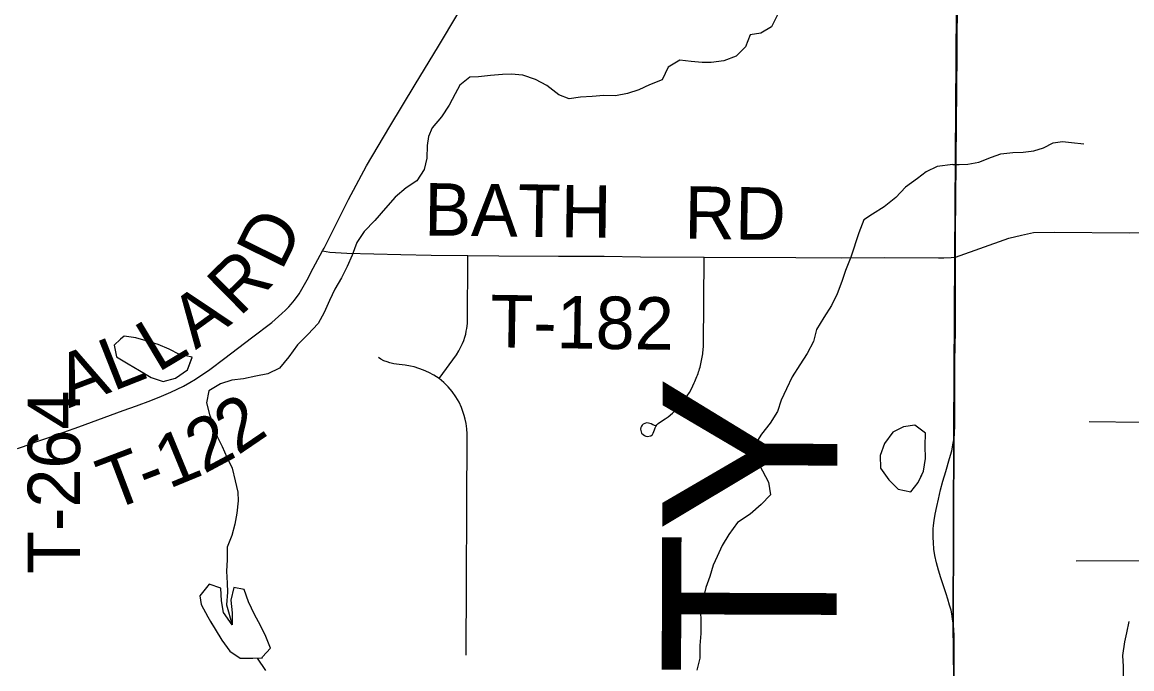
# Model space of a CAD drawing. Extents: x 0 to 34, y 0 to 22.
# Drawn here: x 6.974 to 8.175, y 16.35 to 17.051 of the extents above; entities that cross this region are included whole.
import ezdxf

# ---------------------------------------------------------------- set-up
doc = ezdxf.new("R2010")
doc.units = 0
for name, color, linetype in [('GM_X_Corporation', 7, 'Continuous'), ('GM_X_County_Road', 7, 'Continuous'), ('GM_X_County_Text', 7, 'Continuous'), ('GM_X_Minor_Lake', 7, 'Continuous'), ('GM_X_Minor_River', 7, 'Continuous'), ('GM_X_Township_Road', 7, 'Continuous'), ('GM_X_Township_Road_Text', 7, 'Continuous')]:
    doc.layers.add(name, color=color, linetype=linetype)

msp = doc.modelspace()

# ---------------------------------------------------------------- linework, layer by layer
at = {"layer": 'GM_X_Corporation'}
for points in [[(2.1, 20.9), (2.1, 14.1), (7.9734, 14.1), (7.9726, 14.5453), (7.9765, 15.2637), (7.9792, 15.5481), (7.979, 15.5988), (7.9808, 15.7192), (7.9807, 15.9078), (7.9821, 16.2487), (7.9825, 16.3395), (7.9818, 16.3982), (7.9825, 16.6077), (7.9838, 16.7968), (7.9877, 17.3871), (7.9891, 17.5498), (7.991, 17.7727), (7.9901, 18.1613)], [(7.9901, 18.1613), (7.991, 17.7727), (7.9891, 17.5498), (7.9877, 17.3871), (7.9838, 16.7968), (7.9825, 16.6077), (7.9818, 16.3982), (7.9825, 16.3395), (7.9821, 16.2487), (7.9807, 15.9078), (7.9808, 15.7192), (7.979, 15.5988), (7.9792, 15.5481), (7.9765, 15.2637), (7.9726, 14.5453), (7.9734, 14.1), (8.9, 14.1), (8.9, 20.9)], [(7.9901, 18.1613), (7.991, 17.7727), (7.9891, 17.5498), (7.9877, 17.3871), (7.9838, 16.7968), (7.9825, 16.6077), (7.9818, 16.3982), (7.9825, 16.3395), (7.9821, 16.2487), (7.9807, 15.9078), (7.9808, 15.7192), (7.979, 15.5988), (7.9792, 15.5481), (7.9765, 15.2637), (7.9726, 14.5453), (8.3169, 14.5418), (8.5518, 14.5426), (8.5844, 14.5431), (8.8409, 14.5545), (8.9, 14.5547), (8.9, 19.1229)], [(7.9901, 18.1613), (7.991, 17.7727), (7.9891, 17.5498), (7.9877, 17.3871), (7.9838, 16.7968), (7.9825, 16.6077), (7.9818, 16.3982), (7.9825, 16.3395), (7.9821, 16.2487), (7.9807, 15.9078), (7.9808, 15.7192), (7.979, 15.5988), (7.9792, 15.5481), (7.9765, 15.2637), (7.9726, 14.5453), (7.0871, 14.5429), (7.0197, 14.5427), (6.4941, 14.5412), (6.1476, 14.5397), (5.4644, 14.5374), (4.5212, 14.531)]]:
    msp.add_lwpolyline(points, dxfattribs=at)
at = {"layer": 'GM_X_County_Road'}
for p, q in [((7.9845, 16.7962), (7.9845, 16.7972)), ((7.9845, 16.7782), (7.9845, 16.7962)), ((7.983, 16.3802), (7.983, 16.3839))]:
    msp.add_line(p, q, dxfattribs=at)
for points in [[(7.9845, 16.7972), (7.9845, 16.8156), (7.985, 16.8666), (7.9851, 16.8923), (7.9853, 16.91), (7.9857, 16.9319), (7.9859, 16.9865), (7.9861, 17.0083), (7.9861, 17.0387), (7.9865, 17.06), (7.9862, 17.0801), (7.9861, 17.1071), (7.9863, 17.1552), (7.9869, 17.2019), (7.9869, 17.2365), (7.9873, 17.288), (7.9874, 17.3067), (7.9876, 17.3377), (7.9881, 17.3757), (7.9881, 17.382), (7.9881, 17.3883)], [(7.9845, 16.7962), (8.0423, 16.8166), (8.0561, 16.8201), (8.0688, 16.8228), (8.0916, 16.8232), (8.1729, 16.8224), (8.4609, 16.8258), (8.5768, 16.8284), (8.7668, 16.8308), (8.9, 16.8327)], [(7.9834, 16.6076), (7.9836, 16.6112), (7.9838, 16.6294), (7.9839, 16.6629), (7.9838, 16.6837), (7.9844, 16.7161), (7.9845, 16.744), (7.9845, 16.7782)], [(7.983, 16.3839), (7.9829, 16.3858), (7.9826, 16.393), (7.9819, 16.3995), (7.9813, 16.4041), (7.9804, 16.4098), (7.9796, 16.4138), (7.978, 16.4192), (7.976, 16.4257), (7.9743, 16.4314), (7.9687, 16.4487), (7.9661, 16.457), (7.9638, 16.465), (7.9621, 16.4728), (7.9611, 16.4798), (7.9605, 16.4869), (7.9602, 16.4924), (7.9603, 16.4985), (7.9604, 16.5019), (7.9607, 16.5053), (7.9614, 16.5107), (7.9625, 16.5177), (7.9642, 16.5261), (7.9659, 16.534), (7.9684, 16.5442), (7.9708, 16.5535), (7.9739, 16.564), (7.9781, 16.578), (7.9804, 16.5862), (7.9821, 16.5948), (7.9829, 16.6)], [(7.9829, 16.6), (7.9833, 16.6043), (7.9834, 16.6076)], [(7.9831, 16.3386), (7.9832, 16.3526), (7.983, 16.3802)]]:
    msp.add_lwpolyline(points, dxfattribs=at)
at = {"layer": 'GM_X_Minor_Lake'}
for points in [[(7.0802, 16.7072), (7.073, 16.7009), (7.0757, 16.688), (7.0882, 16.6807), (7.1008, 16.6732), (7.1134, 16.6659), (7.1263, 16.6614), (7.1396, 16.6652), (7.1525, 16.674), (7.1575, 16.6877)], [(7.0802, 16.7072), (7.073, 16.7009), (7.0757, 16.688), (7.0882, 16.6807), (7.1008, 16.6732), (7.1134, 16.6659), (7.1263, 16.6614), (7.1396, 16.6652), (7.1525, 16.674), (7.1575, 16.6876)], [(7.1575, 16.6877), (7.1441, 16.6907), (7.1327, 16.6964), (7.1209, 16.7017), (7.108, 16.7055), (7.0966, 16.7089), (7.084, 16.7104), (7.0802, 16.7072)], [(7.1575, 16.6877), (7.1441, 16.6907), (7.1327, 16.6964), (7.1209, 16.7017), (7.108, 16.7055), (7.0966, 16.7089), (7.084, 16.7104), (7.0802, 16.7072)], [(7.9404, 16.6141), (7.9281, 16.6122), (7.9167, 16.6065), (7.9076, 16.5943), (7.903, 16.5814), (7.9034, 16.5677), (7.9122, 16.5548), (7.9225, 16.5449), (7.9362, 16.5419), (7.9442, 16.5521), (7.9498, 16.5643)], [(7.9403, 16.6141), (7.9281, 16.6122), (7.9167, 16.6065), (7.9076, 16.5943), (7.903, 16.5814), (7.9034, 16.5677), (7.9122, 16.5548), (7.9225, 16.5449), (7.9362, 16.5419), (7.9442, 16.5521), (7.948, 16.5604)], [(7.9478, 16.5599), (7.9498, 16.5643), (7.9521, 16.578), (7.9517, 16.5917), (7.9521, 16.6054), (7.9404, 16.6142)], [(7.9498, 16.5643), (7.9498, 16.5643), (7.9521, 16.578), (7.9517, 16.5917), (7.9521, 16.6054), (7.9404, 16.6141)], [(7.2336, 16.3621), (7.234, 16.363), (7.2424, 16.3725), (7.2374, 16.3851), (7.2317, 16.3972), (7.2252, 16.409), (7.2187, 16.4227), (7.2141, 16.436), (7.2027, 16.4383), (7.1997, 16.4246), (7.2009, 16.4109), (7.2009, 16.3979), (7.1917, 16.4112), (7.1894, 16.4238), (7.1887, 16.4375), (7.1761, 16.442), (7.1658, 16.4291)], [(7.2336, 16.3621), (7.234, 16.363), (7.2424, 16.3725), (7.2374, 16.3851), (7.2317, 16.3972), (7.2252, 16.409), (7.2187, 16.4227), (7.2141, 16.436), (7.2027, 16.4383), (7.1997, 16.4246), (7.2009, 16.4109), (7.2009, 16.3979), (7.1917, 16.4112), (7.1894, 16.4238), (7.1887, 16.4375), (7.1761, 16.442), (7.1658, 16.4291)], [(7.1658, 16.4291), (7.1674, 16.42), (7.1746, 16.4063), (7.1776, 16.4013)], [(7.1771, 16.4017), (7.1826, 16.393), (7.1899, 16.3812), (7.1983, 16.3694), (7.2097, 16.3618), (7.2234, 16.3615), (7.2337, 16.3621)], [(7.1776, 16.4013), (7.1826, 16.393), (7.1899, 16.3812), (7.1983, 16.3694), (7.2097, 16.3618), (7.2234, 16.3615), (7.2336, 16.3621)]]:
    msp.add_lwpolyline(points, dxfattribs=at)
at = {"layer": 'GM_X_Minor_River'}
for points in [[(7.7916, 17.0588), (7.7851, 17.0459), (7.7737, 17.039), (7.7619, 17.0371), (7.757, 17.0242), (7.7468, 17.0139), (7.7334, 17.009), (7.7198, 17.007), (7.7102, 17.007), (7.6981, 17.0082), (7.6859, 17.0097), (7.6733, 17.002), (7.6669, 16.9883), (7.6532, 16.983), (7.6414, 16.9773), (7.6292, 16.9735), (7.6163, 16.9708), (7.6034, 16.9715), (7.5908, 16.9704), (7.5783, 16.9696), (7.5661, 16.9677), (7.5547, 16.9722), (7.5417, 16.9821), (7.5295, 16.9885), (7.5158, 16.9935), (7.5033, 16.9946), (7.4938, 16.9942), (7.4808, 16.9931), (7.4679, 16.9915), (7.4584, 16.9911), (7.4477, 16.9827), (7.4424, 16.9732), (7.436, 16.9607), (7.4276, 16.9481), (7.4177, 16.9363), (7.4136, 16.9268), (7.4121, 16.9173), (7.4117, 16.9036), (7.4091, 16.891), (7.4011, 16.8789), (7.3893, 16.8713), (7.3775, 16.861), (7.3669, 16.8492), (7.3555, 16.8358), (7.3441, 16.824), (7.3361, 16.8119), (7.3308, 16.7985), (7.3255, 16.786), (7.3194, 16.7738), (7.3122, 16.7616), (7.3065, 16.7491), (7.3005, 16.7361), (7.294, 16.7243), (7.283, 16.7125), (7.2716, 16.7011), (7.2625, 16.6882), (7.2522, 16.676), (7.2397, 16.6699), (7.2267, 16.6672), (7.2134, 16.6645), (7.2005, 16.663), (7.1883, 16.6588), (7.1758, 16.6512), (7.1731, 16.6383), (7.1766, 16.6257), (7.1808, 16.6139), (7.1846, 16.6018), (7.1903, 16.5911), (7.1953, 16.5793), (7.201, 16.5676), (7.2041, 16.5539), (7.2071, 16.5417), (7.2075, 16.5322), (7.206, 16.5189), (7.2038, 16.5067), (7.2007, 16.4945), (7.1954, 16.482), (7.1955, 16.4683), (7.1947, 16.4561), (7.1955, 16.4428), (7.1959, 16.4333), (7.1948, 16.4196)], [(7.9816, 16.8965), (7.9884, 16.8965), (7.9978, 16.897), (8.0096, 16.899), (8.0236, 16.9044), (8.0334, 16.9083), (8.0467, 16.9096), (8.0577, 16.9101), (8.0694, 16.9113), (8.0797, 16.9148), (8.0902, 16.9202), (8.1005, 16.9215), (8.11, 16.9204), (8.1233, 16.919)], [(7.9816, 16.8965), (7.9646, 16.8944), (7.9528, 16.8887), (7.9433, 16.8814), (7.9304, 16.8719), (7.9197, 16.8609), (7.9072, 16.8506), (7.8946, 16.8426), (7.8851, 16.8365), (7.8798, 16.8224), (7.8711, 16.7962), (7.8654, 16.7817), (7.8613, 16.7699), (7.8563, 16.7566), (7.8503, 16.7437), (7.8419, 16.7307), (7.8339, 16.7178), (7.8305, 16.7049), (7.8237, 16.6919), (7.8157, 16.6794), (7.8074, 16.6664), (7.8013, 16.6535), (7.7956, 16.6413), (7.7915, 16.6291), (7.7839, 16.6162), (7.7744, 16.6044), (7.7656, 16.5907), (7.7691, 16.5774), (7.7756, 16.5645), (7.7821, 16.5523), (7.784, 16.5386), (7.7741, 16.5283), (7.7619, 16.5177), (7.7483, 16.5085), (7.7391, 16.4956), (7.7316, 16.4838), (7.7262, 16.472), (7.7221, 16.4625), (7.7183, 16.4503), (7.7141, 16.4381), (7.7111, 16.426), (7.7084, 16.4119), (7.7088, 16.4024), (7.7085, 16.3883), (7.7077, 16.3754), (7.7074, 16.3617), (7.7044, 16.3488)], [(7.1948, 16.4196), (7.2009, 16.3979)], [(8.1664, 16.3397), (8.1663, 16.3526), (8.1658, 16.3647), (8.168, 16.3792), (8.1701, 16.3891), (8.1727, 16.4013)], [(7.2375, 16.3482), (7.2285, 16.3618)]]:
    msp.add_lwpolyline(points, dxfattribs=at)
at = {"layer": 'GM_X_Township_Road'}
for points in [[(6.9685, 16.5887), (6.9748, 16.5909), (6.9882, 16.5959), (7.0025, 16.6009), (7.0349, 16.6125), (7.0831, 16.6299), (7.0974, 16.635), (7.1128, 16.641), (7.1245, 16.6456), (7.1346, 16.65), (7.1415, 16.6533), (7.1481, 16.6565), (7.1551, 16.6602), (7.1614, 16.6641), (7.1767, 16.6743), (7.1932, 16.6868), (7.222, 16.7086), (7.2438, 16.7252), (7.2549, 16.735), (7.2588, 16.7386), (7.2623, 16.7423), (7.2649, 16.7452), (7.2684, 16.7495), (7.2734, 16.7566), (7.2822, 16.7716), (7.2888, 16.7843), (7.2989, 16.803), (7.3005, 16.8059), (7.327, 16.8588), (7.3465, 16.8952), (7.3716, 16.9378), (7.3992, 16.9832), (7.4245, 17.0249), (7.4454, 17.0598)], [(7.2989, 16.803), (7.3067, 16.8017), (7.3252, 16.8004), (7.3837, 16.7989), (7.4166, 16.7984), (7.4563, 16.7978), (7.4898, 16.7977), (7.5543, 16.7974), (7.6038, 16.7972), (7.6432, 16.7964), (7.7122, 16.796), (7.8117, 16.7958), (7.8613, 16.7956), (7.9081, 16.7957), (7.966, 16.7953), (7.9717, 16.7954), (7.9799, 16.7957), (7.9845, 16.7962)], [(7.4251, 16.6648), (7.4439, 16.6903), (7.4465, 16.6947), (7.4487, 16.699), (7.4505, 16.7027), (7.4518, 16.7058), (7.4531, 16.7095), (7.454, 16.7127), (7.4546, 16.7159), (7.4552, 16.719), (7.4559, 16.7243), (7.4563, 16.7978)], [(7.6594, 16.6133), (7.6568, 16.6145), (7.6547, 16.6155), (7.652, 16.6163), (7.6499, 16.6165), (7.6478, 16.616), (7.6463, 16.6153), (7.6451, 16.6142), (7.6443, 16.613), (7.6436, 16.6115), (7.6434, 16.6098), (7.6435, 16.6085), (7.6439, 16.607), (7.6445, 16.6055), (7.6462, 16.6039), (7.6475, 16.603), (7.6491, 16.6021), (7.6504, 16.6019), (7.6546, 16.6026), (7.6562, 16.6042), (7.6569, 16.6054), (7.6578, 16.6072), (7.6585, 16.609), (7.6592, 16.6113), (7.6598, 16.6128), (7.661, 16.6146), (7.6624, 16.6158), (7.665, 16.6176), (7.67, 16.6209), (7.6732, 16.6232), (7.6779, 16.6271), (7.6829, 16.6322), (7.6867, 16.6362), (7.6914, 16.6423), (7.6962, 16.6495), (7.6988, 16.6542), (7.7001, 16.6569), (7.7015, 16.66), (7.7022, 16.6616), (7.703, 16.6633), (7.7037, 16.665), (7.7044, 16.6667), (7.705, 16.6684), (7.7056, 16.6701), (7.7062, 16.6718), (7.7068, 16.6735), (7.7073, 16.6753), (7.7078, 16.677), (7.7083, 16.6788), (7.7087, 16.6806), (7.7091, 16.6823), (7.7095, 16.6841), (7.7098, 16.6859), (7.7102, 16.6877), (7.7104, 16.6895), (7.7107, 16.6913), (7.7109, 16.6931), (7.7111, 16.6949), (7.7112, 16.6967), (7.7114, 16.6985), (7.7115, 16.7003), (7.7122, 16.796)], [(7.4545, 16.3648), (7.4554, 16.6049), (7.455, 16.6102), (7.4544, 16.616), (7.4534, 16.6208), (7.4524, 16.6245), (7.4513, 16.628), (7.4495, 16.6332), (7.4468, 16.6392), (7.4433, 16.645), (7.4393, 16.6507), (7.4349, 16.6558), (7.4301, 16.6605), (7.4251, 16.6648), (7.4194, 16.6683), (7.414, 16.6711), (7.4083, 16.6737), (7.4033, 16.6756), (7.3982, 16.6772), (7.3943, 16.6782), (7.3885, 16.6792), (7.3818, 16.6799), (7.3762, 16.6807), (7.3719, 16.6817), (7.3688, 16.6828), (7.3654, 16.684), (7.3622, 16.6858), (7.3595, 16.6875)], [(8.2836, 16.4691), (8.2836, 16.5301), (8.2817, 16.5425), (8.278, 16.5574), (8.2748, 16.5722), (8.2697, 16.5855), (8.2652, 16.593), (8.26, 16.5996), (8.2543, 16.6051), (8.2463, 16.6114), (8.237, 16.6146), (8.2266, 16.6169), (8.2137, 16.6178), (8.1868, 16.6171), (8.1292, 16.6177)], [(8.1151, 16.4672), (8.2497, 16.4676), (8.2836, 16.4691), (8.2983, 16.469), (8.3072, 16.4704), (8.3148, 16.4727), (8.3204, 16.4754), (8.3257, 16.4778), (8.3363, 16.4814), (8.3466, 16.483), (8.3726, 16.4831), (8.4128, 16.4841), (8.4392, 16.4844)]]:
    msp.add_lwpolyline(points, dxfattribs=at)

# ---------------------------------------------------------------- texts
at = {"layer": 'GM_X_County_Text'}
msp.add_text('MEDINA COUNTY', height=0.189394, rotation=89.8023, dxfattribs=at).set_placement((7.8494, 14.542))
at = {"layer": 'GM_X_Township_Road_Text'}
for s, height, rotation, p in [('BATH', 0.05682, 359.2433, (7.4088, 16.8197)), ('RD', 0.05682, 359.0128, (7.6905, 16.8164)), ('D', 0.0568, 63.7502, (7.2544, 16.7802)), ('R', 0.0568, 44.5656, (7.2091, 16.7307)), ('A', 0.0568, 35.8876, (7.1614, 16.6953)), ('T-182', 0.05682, 359.1579, (7.4804, 16.6986)), ('L', 0.0568, 30.8879, (7.1204, 16.6706)), ('L', 0.0568, 21.5324, (7.0718, 16.6505)), ('A', 0.0568, 20.7048, (7.0242, 16.6325)), ('T-264', 0.05682, 90, (7.0363, 16.4531)), ('2', 0.0568, 34.2471, (7.2069, 16.5809)), ('2', 0.0568, 28.1803, (7.1704, 16.5609)), ('1', 0.0568, 22.3711, (7.1324, 16.5449)), ('T', 0.0568, 20.7787, (7.0693, 16.5208)), ('-', 0.0568, 21.0361, (7.1093, 16.536))]:
    msp.add_text(s, height=height, rotation=rotation, dxfattribs=at).set_placement(p)

doc.saveas('drawing.dxf')
